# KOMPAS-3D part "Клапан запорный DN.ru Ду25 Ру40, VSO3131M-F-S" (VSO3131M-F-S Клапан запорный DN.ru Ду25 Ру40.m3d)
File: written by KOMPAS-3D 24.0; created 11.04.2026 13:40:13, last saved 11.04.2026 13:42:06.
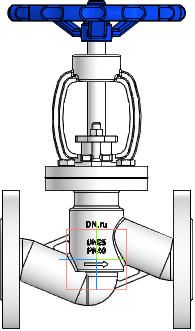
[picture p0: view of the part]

Document properties: Автор: R2D2; Полное имя файла: E:\Работа\Зайцев\VSO3131M-F-S Клапан запорный DN.ru Ду15-100 Ру40\DN25\VSO3131M-F-S Клапан запорный DN.ru Ду25 Ру40.m3d

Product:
- Part/product: Клапан запорный DN.ru Ду25 Ру40  | designation VSO3131M-F-S
    Масса: 5.85
    Раздел спецификации: Прочие изделия
    Примечание: D090-02139

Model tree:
1. Операция без истории:2

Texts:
  VSO3131M-F-S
